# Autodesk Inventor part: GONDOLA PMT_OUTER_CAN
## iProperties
Shininess: 64.0
Length Units: 11272
Angle Units: 11279
Time Units: 11290
Mass Units: 11286
Length Display Precision: 3
Angle Display Precision: 2
Compacted: True
Part Number: GONDOLA PMT_OUTER_CAN
Document SubType Name: Modeling
Created: 2004-08
Designer: John Blackburn
Manufacturer: Standard
Standards Organization: Custom
Material: Steel, Mild
Density: 0.0
Volumn: 0.0
Area: 0.0
PropertySet Name: Model Information
Control State: 0
Master: False
Checked Out: False
Author: John Blackburn
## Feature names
1. Base1
